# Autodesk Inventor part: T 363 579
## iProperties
Created: 2005-12
Part Number: T 363 579
Material: 1.4301
Document SubType Name: Sheet Metal
Designer: I.Baliuc
Manufacturer: Standard
Standards Organization: Custom
Description: Vorkontaktträger
Density: 7.86 g/cm^3
Sheet Metal Rule: Standard
Title: Vorkontaktträger
Company: Mayer & Müller AG Schaltgeräte
Author: T.Messerschmitt
Revision Number: 363579
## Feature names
1. Bohrung1 [Hole]
2. Bohrung2 [Hole]
3. Spiegeln1 [Mirror]
4. Bohrung3 [Hole]
5. Grobblech1
6. Grobblech2
7. Biegung1
8. Grobblech3
9. Biegung2
10. Ausschneiden1
